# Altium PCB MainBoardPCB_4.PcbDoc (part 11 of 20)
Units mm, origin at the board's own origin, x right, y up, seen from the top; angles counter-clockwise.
Board outline 333.63 x 349.38 mm, 16 copper layers (L1, L2 (GND), L3 (Sign), L4 (GND), L5 (Sign), L6 (PWR/GND), L7(PWR/GND), L8 (Plane_GND), L9 (PWR/GND), L10 (PWR/GND), L11 (PWR/GND), L12 (Sign), L13 (GND), L14 (Sign), L15 (GND), L16), stack 2.502 mm thick; 2205 components, 1648 nets, 8314 pads, 3172 vias.
Unrouted connection lines stored in the file: 5141.
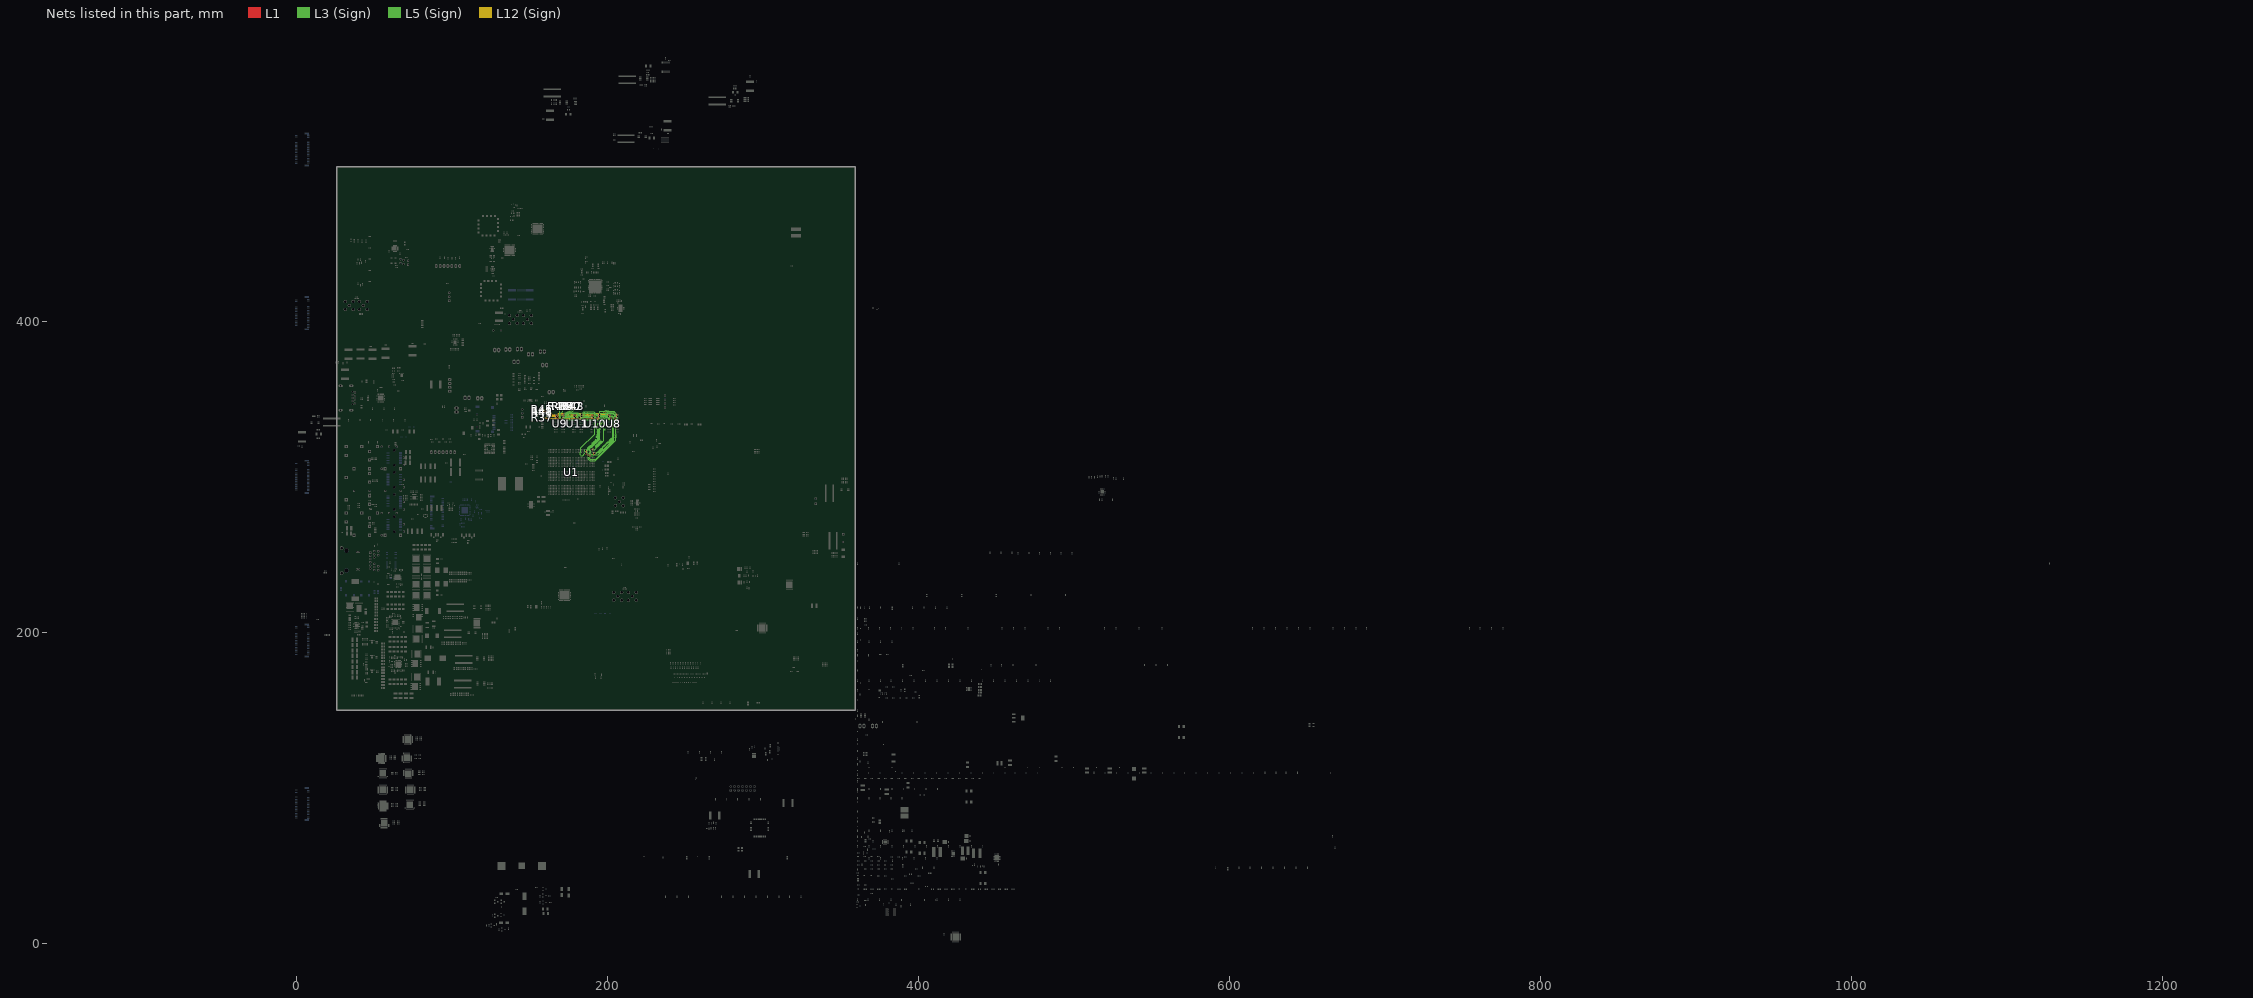
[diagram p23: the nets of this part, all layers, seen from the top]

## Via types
v1: diameter 0.5, hole 0.2, L1 to L16, tented both sides, 1153 vias
v2: diameter 0.5/0.35/0.35/0.35/0.35/0.35/0.35/0.35/0.35/0.35/0.35/0.35/0.35/0.35/0.35/0.5 (per signal layer), hole 0.2, L1 to L16, tented both sides, 548 vias
v3: diameter 0.5, hole 0.2, L1 to L16, 522 vias
v4: diameter 0.5/0.35/0.35/0.35/0.35/0.35/0.35/0.35/0.35/0.35/0.35/0.35/0.35/0.35/0.35/0.5 (per signal layer), hole 0.15, L1 to L16, tented both sides, 266 vias
v5: diameter 0.8, hole 0.4, L1 to L16, tented both sides, 164 vias
v6: diameter 0.35/0/0.35 (per signal layer), hole 0.127, L1 to L3 (Sign), tented both sides, 132 vias
v7: diameter 2.54, hole 1.02, L1 to L16, 125 vias
v8: diameter 1.4, hole 0.5, L1 to L16, tented both sides, 80 vias
v9: diameter 0.35, hole 0.127, L1 to L2 (GND), tented both sides, 36 vias
v10: diameter 0.4, hole 0.2, L1 to L16, 16 vias
v11: diameter 0.25, hole 0.2, L1 to L16, 16 vias
v12: diameter 5, hole 3, L1 to L16, 15 vias
v13: diameter 0.3, hole 0.2, L1 to L16, 15 vias
v14: diameter 0.45, hole 0.15, L1 to L16, 12 vias
v15: diameter 0.5/0.35/0.35/0.35/0.35/0.35/0.35/0.35/0.35/0.35/0.35/0.35/0.35/0.35/0.35/0.45 (per signal layer), hole 0.15, L1 to L16, tented both sides, 10 vias
v16: diameter 0.2/0/0.2 (per signal layer), hole 0.1, L1 to L3 (Sign), tented both sides, 9 vias
v17: diameter 0.4, hole 0.1, L1 to L16, 7 vias
v18: diameter 0.5, hole 0.2, L3 (Sign) to L6 (PWR/GND), tented both sides, 6 vias
v19: diameter 1.65, hole 1.65, L1 to L16, 6 vias
v20: diameter 1.15, hole 1.15, L1 to L16, 6 vias
v21: diameter 0.35/0/0.35 (per signal layer), hole 0.127, L14 (Sign) to L16, tented both sides, 5 vias
v22: diameter 0.2, hole 0.1, L1 to L16, 4 vias
v23: diameter 0.4, hole 0.2, L1 to L16, tented both sides, 2 vias
v24: diameter 0.4, hole 0.15, L1 to L16, 2 vias
v25: diameter 0.508, hole 0.127, L1 to L2 (GND), 2 vias
v26: diameter 0.508, hole 0.127, L2 (GND) to L3 (Sign), 2 vias
v27: diameter 0.5/0.35/0.35/0.35/0.35/0.35/0.35/0.35/0.35/0.35/0.35/0.35/0.35/0.35/0.35/0.5 (per signal layer), hole 0.15, L1 to L16, 2 vias
v28: diameter 0.35, hole 0.127, L3 (Sign) to L6 (PWR/GND), tented both sides, 2 vias
v29: diameter 5.5, hole 3.5, L1 to L16, 1 vias
v30: diameter 0.5/0.35/0.35/0.35/0.35/0.35/0.35/0.35/0.35/0.35/0.35/0.35/0.35/0.35/0.35/0.5 (per signal layer), hole 0.2, L1 to L16, 1 vias
v31: diameter 0.35/0.35/0.35 (per signal layer), hole 0.127, L1 to L3 (Sign), tented both sides, 1 vias
v32: diameter 0.45/0/0.45 (per signal layer), hole 0.15, L1 to L3 (Sign), tented both sides, 1 vias
v33: diameter 0.45/0/0.45 (per signal layer), hole 0.2, L14 (Sign) to L16, tented both sides, 1 vias
v34: diameter 0.35, hole 0.127, L2 (GND) to L3 (Sign), 1 vias
v35: diameter 0.35, hole 0.127, L1 to L2 (GND), 1 vias

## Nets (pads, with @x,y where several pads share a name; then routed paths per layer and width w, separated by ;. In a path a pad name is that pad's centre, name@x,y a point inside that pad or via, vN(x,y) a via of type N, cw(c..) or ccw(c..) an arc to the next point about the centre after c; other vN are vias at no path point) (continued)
DDR4_A3: R37.1 U1.AJ30 U8.N4 U9.N4 U10.N4 U11.N4 | length 99.3
  L1 w0.116: U9.N4@167.676,337.66 168.072,338.057 v4(168.075,338.057) ; U11.N4@179.136,337.66 179.533,338.057 v4(179.535,338.057) ; U1.AJ30@190.397,317.539 v6(190.884,318.027) ; U10.N4@190.597,337.66 190.993,338.057 v4(190.995,338.057) ; U8.N4@202.057,337.66 202.453,338.057 v4(202.456,338.057)
  L1 w0.155: R37.1@158.737,337.967 v1(159.982,337.967)
  L12 (Sign) w0.092: 165.251,337.661 166.76,337.661 167.508,337.661 167.896,338.049 v4(168.075,338.057) ; v4@168.075,338.049 168.821,338.049 169.171,337.698 173.927,337.698 175.389,337.698 cw(c175.389,337.609) 175.479,337.609 175.479,337.545 ccw(c175.568,337.545) 175.568,337.456 175.837,337.456 ccw(c175.837,337.545) 175.927,337.545 175.927,337.698 175.927,337.773 cw(c176.016,337.773) 176.016,337.863 176.285,337.863 cw(c176.285,337.773) 176.374,337.773 176.374,337.698 176.374,337.545 ccw(c176.464,337.545) 176.464,337.456 176.733,337.456 ccw(c176.733,337.545) 176.822,337.545 176.822,337.609 cw(c176.912,337.609) 176.912,337.698 177.046,337.698 177.931,337.698 177.934,337.695 178.053,337.695 178.053,337.698 178.201,337.698 178.201,337.695 178.32,337.695 178.323,337.698 178.831,337.698 179.189,338.057 v4@179.533,338.057 ; v4(179.535,338.057) 180.56,338.057 180.95,337.668 184.651,337.668 185.134,338.15 186.39,338.15 186.616,338.15 cw(c186.616,338.081) 186.685,338.081 186.685,337.958 ccw(c186.754,337.958) 186.754,337.889 186.962,337.889 ccw(c186.962,337.958) 187.031,337.958 187.031,338.15 187.031,338.183 cw(c187.1,338.183) 187.1,338.252 187.308,338.252 cw(c187.308,338.183) 187.377,338.183 187.377,338.15 187.377,337.958 ccw(c187.446,337.958) 187.446,337.889 187.654,337.889 ccw(c187.654,337.958) 187.723,337.958 187.723,338.081 cw(c187.793,338.081) 187.793,338.15 187.897,338.15 189.219,338.15 189.633,337.736 190.504,337.736 190.817,338.049 191.312,338.049 191.662,337.698 193.827,337.698 194.311,337.698 cw(c194.311,337.609) 194.4,337.609 ; 194.4,337.608 ccw(c194.49,337.608) 194.49,337.519 194.759,337.519 ccw(c194.759,337.608) 194.848,337.608 ; 194.848,337.609 cw(c194.938,337.609) 194.938,337.698 195.072,337.698 195.123,337.698 195.458,337.363 196.532,337.363 197.232,337.363 cw(c197.232,337.273) 197.321,337.273 197.321,337.214 ccw(c197.411,337.214) 197.411,337.125 197.68,337.125 ccw(c197.68,337.214) 197.769,337.214 197.769,337.273 cw(c197.859,337.273) 197.859,337.363 197.993,337.363 198.352,337.363 ccw(c198.352,337.452) 198.442,337.452 198.442,337.5 cw(c198.531,337.5) 198.531,337.59 198.8,337.59 cw(c198.8,337.5) 198.89,337.5 198.89,337.363 198.89,337.214 ccw(c198.979,337.214) 198.979,337.125 199.248,337.125 ccw(c199.248,337.214) 199.337,337.214 199.337,337.363 cw(c199.427,337.363) 199.427,337.452 199.696,337.452 cw(c199.696,337.363) 199.785,337.363 199.785,337.214 ccw(c199.875,337.214) 199.875,337.125 200.143,337.125 ccw(c200.143,337.214) 200.233,337.214 200.233,337.273 cw(c200.322,337.273) 200.322,337.363 200.457,337.363 201.112,337.363 201.447,337.698 202.097,337.698 v4(202.456,338.057)
  L12 (Sign) w0.151: v1(159.982,337.967) 160.623,337.967 160.928,337.661 165.251,337.661
  L3 (Sign) w0.092: v6(190.884,318.027) 190.884,317.789 191.329,317.344 191.726,317.344 191.867,317.484 192.147,317.765 192.428,318.046 192.709,318.327 192.919,318.537 ccw(c192.849,318.607) 192.919,318.677 192.123,319.474 cw(c192.193,319.544) 192.123,319.614 192.263,319.755 cw(c192.333,319.684) 192.403,319.755 193.2,318.958 ccw(c193.27,319.028) 193.34,318.958 193.481,319.099 ccw(c193.411,319.169) 193.481,319.239 192.684,320.035 cw(c192.754,320.106) 192.684,320.176 192.825,320.316 cw(c192.895,320.246) 192.965,320.316 193.761,319.52 ccw(c193.832,319.59) 193.902,319.52 194.042,319.66 ccw(c193.972,319.73) 194.042,319.8 193.246,320.597 cw(c193.316,320.667) 193.246,320.737 193.386,320.878 cw(c193.456,320.807) 193.526,320.878 194.323,320.081 ccw(c194.393,320.151) 194.463,320.081 194.604,320.221 ccw(c194.533,320.292) 194.604,320.362 193.807,321.158 cw(c193.877,321.228) 193.807,321.299 193.947,321.439 cw(c194.018,321.369) 194.088,321.439 194.884,320.642 ccw(c194.954,320.713) 195.025,320.642 195.165,320.783 ccw(c195.095,320.853) 195.165,320.923 194.368,321.72 cw(c194.439,321.79) 194.368,321.86 194.509,322 cw(c194.579,321.93) 194.649,322 195.446,321.204 ccw(c195.516,321.274) 195.586,321.204 195.726,321.344 ccw(c195.656,321.414) 195.726,321.485 194.93,322.281 cw(c195,322.351) 194.93,322.422 195.07,322.562 cw(c195.14,322.492) 195.211,322.562 196.007,321.765 ccw(c196.077,321.836) 196.148,321.765 196.288,321.906 ccw(c196.218,321.976) 196.288,322.046 195.491,322.843 cw(c195.562,322.913) 195.491,322.983 195.632,323.123 cw(c195.702,323.053) 195.772,323.123 196.569,322.327 ccw(c196.639,322.397) 196.709,322.327 196.92,322.537 197.2,322.818 197.574,323.192 197.574,329.171 197.574,330.229 cw(c197.673,330.229) 197.673,330.328 198.456,330.328 ccw(c198.456,330.427) 198.555,330.427 198.555,330.626 ccw(c198.456,330.626) 198.456,330.725 197.574,330.725 cw(c197.574,330.824) 197.475,330.824 197.475,331.023 cw(c197.574,331.023) 197.574,331.122 197.75,331.122 ccw(c197.75,331.221) 197.849,331.221 197.849,331.42 ccw(c197.75,331.42) 197.75,331.519 197.574,331.519 cw(c197.574,331.618) 197.475,331.618 197.475,331.817 cw(c197.574,331.817) 197.574,331.916 ccw(c197.574,332.015) 197.673,332.015 197.673,332.214 ccw(c197.574,332.214) 197.574,332.313 197.574,332.511 197.574,334.379 200.822,337.627 202.026,337.627 v4(202.456,338.057)
DDR4_A4: R39.1 U1.AK28 U8.N3 U9.N3 U10.N3 U11.N3 | length 98.4
  L1 w0.116: v4(170.472,338.064) U9.N3@170.876,337.66 ; v30(181.933,338.064) U11.N3@182.336,337.66 ; U1.AK28@191.397,315.539 v6(192.086,315.539) ; v4(193.393,338.064) U10.N3@193.797,337.66 ; v15(204.853,338.064) U8.N3@205.257,337.66
  L1 w0.155: v1(171.229,343.555) R39.1@171.229,344.8
  L5 (Sign) w0.092: 170.437,341.085 169.784,340.433 169.784,338.752 v4(170.472,338.064) 171.003,338.064 171.4,338.46 173.698,338.46 173.832,338.46 ccw(c173.832,338.55) 173.922,338.55 173.922,338.672 cw(c174.011,338.672) 174.011,338.762 174.28,338.762 cw(c174.28,338.672) 174.37,338.672 174.37,338.46 174.37,338.249 ccw(c174.459,338.249) 174.459,338.159 174.728,338.159 ccw(c174.728,338.249) 174.817,338.249 174.817,338.371 cw(c174.907,338.371) 174.907,338.46 175.997,338.46 180.482,338.46 180.878,338.064 v30(181.933,338.064) 182.713,338.064 183.109,338.46 185.801,338.46 185.974,338.46 186.251,338.46 cw(c186.251,338.391) 186.32,338.391 186.32,338.15 ccw(c186.39,338.15) 186.39,338.081 186.597,338.081 ccw(c186.597,338.15) 186.666,338.15 186.666,338.46 186.666,338.77 cw(c186.736,338.77) 186.736,338.84 186.943,338.84 cw(c186.943,338.77) 187.013,338.77 187.013,338.53 ccw(c187.082,338.53) 187.082,338.46 187.82,338.46 191.942,338.46 192.339,338.064 v4(193.393,338.064) 193.924,338.064 194.366,338.506 194.564,338.506 196.327,338.506 cw(c196.327,338.416) 196.417,338.416 196.417,338.348 ccw(c196.506,338.348) 196.506,338.258 196.775,338.258 ccw(c196.775,338.348) 196.864,338.348 196.864,338.506 196.864,338.82 cw(c196.954,338.82) 196.954,338.91 197.223,338.91 cw(c197.223,338.82) 197.312,338.82 197.312,338.595 ccw(c197.402,338.595) 197.402,338.506 197.67,338.506 ccw(c197.67,338.595) 197.76,338.595 197.76,338.82 cw(c197.849,338.82) 197.849,338.91 198.118,338.91 cw(c198.118,338.82) 198.208,338.82 198.208,338.595 ccw(c198.297,338.595) 198.297,338.506 198.566,338.506 ccw(c198.566,338.595) 198.656,338.595 198.656,338.82 cw(c198.745,338.82) 198.745,338.91 199.014,338.91 cw(c199.014,338.82) 199.103,338.82 199.103,338.595 ccw(c199.193,338.595) 199.193,338.506 199.462,338.506 ccw(c199.462,338.595) 199.551,338.595 199.551,338.82 cw(c199.641,338.82) 199.641,338.91 199.909,338.91 cw(c199.909,338.82) 199.999,338.82 199.999,338.595 ccw(c200.088,338.595) 200.088,338.506 200.447,338.506 200.805,338.506 cw(c200.805,338.416) 200.895,338.416 200.895,338.348 ccw(c200.984,338.348) 200.984,338.258 201.253,338.258 ccw(c201.253,338.348) 201.342,338.348 201.342,338.416 cw(c201.432,338.416) 201.432,338.506 201.701,338.506 cw(c201.701,338.416) 201.79,338.416 201.79,338.403 ccw(c201.88,338.403) 201.88,338.314 202.148,338.314 ccw(c202.148,338.403) 202.238,338.403 202.238,338.506 202.238,338.82 cw(c202.327,338.82) 202.327,338.91 202.596,338.91 cw(c202.596,338.82) 202.686,338.82 202.686,338.506 202.686,338.317 ccw(c202.775,338.317) 202.775,338.227 203.044,338.227 ccw(c203.044,338.317) 203.134,338.317 203.134,338.416 cw(c203.223,338.416) 203.223,338.506 203.357,338.506 203.799,338.064 v15(204.853,338.064)
  L5 (Sign) w0.151: 170.437,341.085 171.229,341.878 v1(171.229,343.555)
  L3 (Sign) w0.092: v6(192.086,315.539) 192.317,315.539 192.416,315.539 ccw(c192.416,315.639) 192.515,315.639 192.515,315.688 cw(c192.615,315.688) 192.615,315.787 192.813,315.787 cw(c192.813,315.688) 192.912,315.688 192.912,315.539 192.912,315.189 ccw(c193.012,315.189) 193.012,315.089 193.21,315.089 ccw(c193.21,315.189) 193.309,315.189 193.309,315.44 cw(c193.409,315.44) 193.409,315.539 193.543,315.539 193.684,315.68 ; 193.683,315.68 cw(c193.753,315.75) 193.683,315.821 193.823,315.961 cw(c193.894,315.891) 193.964,315.961 ; 193.964,315.961 194.466,315.459 ccw(c194.536,315.529) 194.606,315.459 194.746,315.6 ccw(c194.676,315.67) 194.746,315.74 194.245,316.241 cw(c194.312,316.309) 194.245,316.376 194.391,316.522 cw(c194.458,316.454) 194.526,316.522 195.027,316.021 ccw(c195.097,316.091) 195.167,316.021 195.308,316.161 ccw(c195.238,316.231) 195.308,316.301 194.806,316.803 cw(c194.874,316.87) 194.806,316.938 194.952,317.083 cw(c195.02,317.016) 195.087,317.083 195.588,316.582 ccw(c195.659,316.652) 195.729,316.582 195.869,316.722 ccw(c195.799,316.793) 195.869,316.863 195.368,317.364 cw(c195.435,317.432) 195.368,317.499 195.514,317.645 cw(c195.581,317.577) 195.649,317.645 196.15,317.144 ccw(c196.22,317.214) 196.29,317.144 196.431,317.284 ccw(c196.36,317.354) 196.431,317.424 195.929,317.926 cw(c195.997,317.993) 195.929,318.06 196.075,318.206 cw(c196.143,318.139) 196.21,318.206 196.711,317.705 ccw(c196.782,317.775) 196.852,317.705 196.992,317.845 ccw(c196.922,317.916) 196.992,317.986 196.491,318.487 cw(c196.558,318.554) 196.491,318.622 196.637,318.768 cw(c196.704,318.7) 196.772,318.768 196.848,318.691 ccw(c196.919,318.761) 196.989,318.691 197.129,318.831 ccw(c197.059,318.901) 197.129,318.971 197.052,319.048 cw(c197.12,319.116) 197.052,319.183 197.198,319.329 cw(c197.265,319.262) 197.333,319.329 197.41,319.252 ccw(c197.48,319.322) 197.55,319.252 197.691,319.393 ccw(c197.62,319.463) 197.691,319.533 197.614,319.61 cw(c197.681,319.677) 197.614,319.745 197.759,319.891 cw(c197.827,319.823) 197.894,319.891 197.971,319.814 ccw(c198.042,319.884) 198.112,319.814 198.252,319.954 ccw(c198.182,320.024) 198.252,320.094 198.175,320.171 cw(c198.243,320.239) 198.175,320.306 198.321,320.452 cw(c198.388,320.385) 198.456,320.452 198.533,320.375 ccw(c198.603,320.445) 198.673,320.375 198.814,320.515 ccw(c198.743,320.586) 198.814,320.656 198.737,320.733 cw(c198.804,320.8) 198.737,320.868 198.882,321.013 cw(c198.95,320.946) 199.017,321.013 199.094,320.937 ccw(c199.164,321.007) 199.235,320.937 199.375,321.077 ccw(c199.305,321.147) 199.375,321.217 199.298,321.294 cw(c199.365,321.362) 199.298,321.429 199.444,321.575 cw(c199.511,321.507) 199.579,321.575 199.656,321.498 ccw(c199.726,321.568) 199.796,321.498 199.936,321.638 ccw(c199.866,321.709) 199.936,321.779 199.859,321.856 cw(c199.927,321.923) 199.859,321.991 200.005,322.136 cw(c200.073,322.069) 200.14,322.136 200.354,321.923 ccw(c200.424,321.993) 200.494,321.923 200.635,322.063 ccw(c200.564,322.133) 200.635,322.203 200.421,322.417 cw(c200.488,322.485) 200.421,322.552 200.567,322.698 cw(c200.634,322.63) 200.702,322.698 200.867,322.532 ccw(c200.938,322.602) 201.008,322.532 201.148,322.672 ccw(c201.078,322.743) 201.148,322.813 200.982,322.979 cw(c201.05,323.046) 200.982,323.113 201.128,323.259 cw(c201.196,323.192) 201.263,323.259 201.429,323.094 ccw(c201.499,323.164) 201.569,323.094 201.71,323.234 ccw(c201.639,323.304) 201.71,323.374 201.544,323.54 cw(c201.611,323.607) 201.544,323.675 201.69,323.821 cw(c201.757,323.753) 201.824,323.821 201.99,323.655 ccw(c202.06,323.725) 202.131,323.655 202.271,323.795 ccw(c202.201,323.865) 202.271,323.936 202.105,324.101 cw(c202.173,324.169) 202.105,324.236 202.251,324.382 cw(c202.318,324.315) 202.386,324.382 202.552,324.216 ccw(c202.622,324.287) 202.692,324.216 202.832,324.357 ccw(c202.762,324.427) 202.832,324.497 202.737,324.593 cw(c202.807,324.663) 202.737,324.733 202.927,324.923 203.434,325.43 203.434,335.975 203.707,336.248 203.707,338.149 203.987,338.43 204.642,338.43 204.853,338.218 v15(204.853,338.064)
DDR4_A5: R41.1 U1.AK27 U8.P5 U9.P5 U10.P5 U11.P5 | length 98
  L1 w0.116: U9.P5@166.876,338.46 167.272,338.857 v4(167.275,338.857) ; U11.P5@178.336,338.46 178.733,338.857 v4(178.735,338.857) ; U10.P5@189.797,338.46 190.193,338.857 v4(190.196,338.857) ; U1.AK27@191.397,314.539 v6(191.884,315.027) ; v4(200.853,338.864) U8.P5@201.257,338.46
  L1 w0.155: R41.1@158.737,341.233 v1(159.982,341.233)
  L12 (Sign) w0.092: 165.251,338.857 166.751,338.857 v4(167.275,338.857) 167.465,339.047 167.688,339.047 167.842,339.201 168.3,339.201 169.159,340.06 173.807,340.06 174.282,339.585 174.472,339.395 cw(c174.409,339.332) 174.472,339.269 174.437,339.233 ccw(c174.5,339.17) 174.437,339.106 174.627,338.916 ccw(c174.69,338.98) 174.753,338.916 174.789,338.952 cw(c174.852,338.889) 174.915,338.952 175.01,338.857 v4(178.735,338.857) 179.053,338.857 179.451,339.255 180.302,339.255 181.127,340.081 184.125,340.081 184.945,339.26 186.576,339.26 187.06,339.26 cw(c187.06,339.191) 187.129,339.191 187.129,339.18 ccw(c187.199,339.18) 187.199,339.111 187.406,339.111 ccw(c187.406,339.18) 187.476,339.18 187.476,339.26 187.476,339.337 cw(c187.545,339.337) 187.545,339.407 187.752,339.407 cw(c187.752,339.337) 187.822,339.337 187.822,339.26 187.822,339.18 ccw(c187.891,339.18) 187.891,339.111 188.099,339.111 ccw(c188.099,339.18) 188.168,339.18 188.168,339.191 cw(c188.237,339.191) 188.237,339.26 188.341,339.26 189.268,339.26 189.672,338.857 v4(190.196,338.857) 190.385,339.047 190.609,339.047 190.763,339.201 191.22,339.201 192.08,340.06 195.846,340.06 196.524,339.382 197.193,339.382 198.16,339.382 cw(c198.16,339.293) 198.25,339.293 198.25,338.968 ccw(c198.339,338.968) 198.339,338.878 198.608,338.878 ccw(c198.608,338.968) 198.697,338.968 198.697,339.382 198.697,339.496 cw(c198.787,339.496) 198.787,339.586 199.056,339.586 cw(c199.056,339.496) 199.145,339.496 199.145,339.382 199.145,338.968 ccw(c199.235,338.968) 199.235,338.878 199.504,338.878 ccw(c199.504,338.968) 199.593,338.968 199.593,339.293 cw(c199.683,339.293) 199.683,339.382 199.817,339.382 200.342,338.857 v4@200.861,338.857
  L12 (Sign) w0.151: v1(159.982,341.233) 160.607,341.233 161.446,340.395 161.491,340.395 163.029,338.857 165.251,338.857
  L3 (Sign) w0.092: 189.328,315.928 189.328,316.31 188.563,317.074 188.563,318.187 188.633,318.257 ccw(c188.563,318.327) 188.633,318.398 188.63,318.401 cw(c188.701,318.471) 188.63,318.541 188.771,318.681 cw(c188.841,318.611) 188.911,318.681 188.984,318.608 189.016,318.576 ccw(c189.087,318.646) 189.157,318.576 189.297,318.717 ccw(c189.227,318.787) 189.297,318.857 189.265,318.889 189.192,318.962 cw(c189.262,319.032) 189.192,319.103 189.332,319.243 cw(c189.402,319.173) 189.473,319.243 189.546,319.17 189.786,318.929 ccw(c189.856,319) 189.926,318.929 190.067,319.07 ccw(c189.997,319.14) 190.067,319.21 189.827,319.45 189.753,319.524 cw(c189.823,319.594) 189.753,319.664 189.894,319.804 cw(c189.964,319.734) 190.034,319.804 190.107,319.731 190.347,319.491 ccw(c190.418,319.561) 190.488,319.491 190.628,319.631 ccw(c190.558,319.701) 190.628,319.772 190.388,320.012 190.315,320.085 cw(c190.385,320.155) 190.315,320.225 190.455,320.366 cw(c190.525,320.296) 190.595,320.366 190.669,320.293 190.909,320.052 ccw(c190.979,320.123) 191.049,320.052 191.19,320.193 ccw(c191.119,320.263) 191.19,320.333 190.949,320.573 190.876,320.647 cw(c190.946,320.717) 190.876,320.787 191.016,320.927 cw(c191.087,320.857) 191.157,320.927 191.23,320.854 191.47,320.614 ccw(c191.54,320.684) 191.611,320.614 191.751,320.754 ccw(c191.681,320.824) 191.751,320.895 191.511,321.135 191.438,321.208 cw(c191.508,321.278) 191.438,321.348 191.578,321.489 cw(c191.648,321.419) 191.718,321.489 191.792,321.415 192.032,321.175 ccw(c192.102,321.245) 192.172,321.175 192.312,321.316 ccw(c192.242,321.386) 192.312,321.456 192.072,321.696 191.999,321.769 cw(c192.069,321.84) 191.999,321.91 192.139,322.05 cw(c192.21,321.98) 192.28,322.05 192.353,321.977 192.593,321.737 ccw(c192.663,321.807) 192.734,321.737 192.874,321.877 ccw(c192.804,321.947) 192.874,322.017 192.634,322.258 192.56,322.331 cw(c192.631,322.401) 192.56,322.471 192.701,322.612 cw(c192.771,322.541) 192.841,322.612 192.914,322.538 193.155,322.298 ccw(c193.225,322.368) 193.295,322.298 193.435,322.439 ccw(c193.365,322.509) 193.435,322.579 193.195,322.819 193.122,322.892 cw(c193.192,322.962) 193.122,323.033 193.262,323.173 cw(c193.332,323.103) 193.403,323.173 193.476,323.1 193.716,322.86 ccw(c193.786,322.93) 193.856,322.86 193.997,323 ccw(c193.927,323.07) 193.997,323.14 193.757,323.38 193.683,323.454 cw(c193.754,323.524) 193.683,323.594 193.824,323.734 cw(c193.894,323.664) 193.964,323.734 194.037,323.661 194.278,323.421 ccw(c194.348,323.491) 194.418,323.421 194.558,323.561 ccw(c194.488,323.632) 194.558,323.702 194.318,323.942 194.245,324.015 cw(c194.315,324.085) 194.245,324.156 194.385,324.296 cw(c194.455,324.226) 194.526,324.296 194.599,324.223 194.839,323.982 ccw(c194.909,324.053) 194.979,323.982 195.12,324.123 ccw(c195.049,324.193) 195.12,324.263 194.95,324.433 cw(c195.02,324.503) 194.95,324.574 195.212,324.836 195.212,330.648 195.631,331.067 195.631,331.483 196.438,332.29 196.438,334.652 200.643,338.857 200.861,338.857 v4(200.853,338.864) ; 189.332,315.928 189.332,315.746 188.956,315.37 188.907,315.37 188.718,315.182 188.718,314.916 188.907,314.728 189.391,314.728 189.605,314.514 190.167,314.514 190.322,314.668 191.091,314.668 191.271,314.847 191.271,315.413 191.419,315.562 191.671,315.562 191.711,315.522 191.711,315.2 v6(191.884,315.027)
DDR4_A6: R43.1 U1.AF27 U8.P2 U9.P2 U10.P2 U11.P2 | length 102.8
  L1 w0.116: U9.P2@171.676,338.46 v4(172.079,338.864) ; U11.P2@183.136,338.46 v4(183.54,338.864) ; U1.AF27@187.397,314.539 v6(187.884,314.052) ; U10.P2@194.597,338.46 v4(195,338.864) ; U8.P2@206.057,338.46 v4(206.461,338.864)
  L1 w0.155: v6(178.481,343.555) R43.1@178.481,344.799
  L5 (Sign) w0.092: v4(172.079,338.864) 173.515,338.864 173.911,339.26 174.6,339.26 174.734,339.26 ccw(c174.734,339.35) 174.823,339.35 174.823,339.393 cw(c174.913,339.393) 174.913,339.482 175.182,339.482 cw(c175.182,339.393) 175.271,339.393 175.271,339.26 175.271,339.128 ccw(c175.361,339.128) 175.361,339.039 175.63,339.039 ccw(c175.63,339.128) 175.719,339.128 175.719,339.171 cw(c175.809,339.171) 175.809,339.26 176.187,339.26 180.228,339.26 181.008,338.48 182.583,338.48 182.966,338.864 v4(183.54,338.864) 183.839,338.864 184.217,339.242 184.404,339.242 184.577,339.242 184.854,339.242 cw(c184.854,339.173) 184.923,339.173 184.923,339.008 ccw(c184.993,339.008) 184.993,338.939 185.2,338.939 ccw(c185.2,339.008) 185.269,339.008 185.269,339.242 185.269,339.477 cw(c185.339,339.477) 185.339,339.546 185.546,339.546 cw(c185.546,339.477) 185.616,339.477 185.616,339.312 ccw(c185.685,339.312) 185.685,339.242 186.195,339.242 191.707,339.242 192.469,338.48 194.043,338.48 194.427,338.864 v4(195,338.864) 195.227,338.864 195.623,339.26 195.77,339.26 196.189,339.26 cw(c196.189,339.171) 196.279,339.171 196.279,339.017 ccw(c196.369,339.017) 196.369,338.927 196.637,338.927 ccw(c196.637,339.017) 196.727,339.017 196.727,339.26 196.727,339.523 cw(c196.816,339.523) 196.816,339.613 197.085,339.613 cw(c197.085,339.523) 197.175,339.523 197.175,339.26 197.175,339.192 ccw(c197.264,339.192) 197.264,339.103 197.533,339.103 ccw(c197.533,339.192) 197.622,339.192 197.622,339.26 197.622,339.523 cw(c197.712,339.523) 197.712,339.613 197.981,339.613 cw(c197.981,339.523) 198.07,339.523 198.07,339.26 198.07,339.192 ccw(c198.16,339.192) 198.16,339.103 198.428,339.103 ccw(c198.428,339.192) 198.518,339.192 198.518,339.26 198.518,339.523 cw(c198.608,339.523) 198.608,339.613 198.876,339.613 cw(c198.876,339.523) 198.966,339.523 198.966,339.26 198.966,339.192 ccw(c199.055,339.192) 199.055,339.103 199.324,339.103 ccw(c199.324,339.192) 199.414,339.192 199.414,339.26 199.414,339.523 cw(c199.503,339.523) 199.503,339.613 199.772,339.613 cw(c199.772,339.523) 199.861,339.523 199.861,339.26 199.861,339.192 ccw(c199.951,339.192) 199.951,339.103 200.22,339.103 ccw(c200.22,339.192) 200.309,339.192 200.309,339.26 200.309,339.295 cw(c200.399,339.295) 200.399,339.385 200.667,339.385 cw(c200.667,339.295) 200.757,339.295 200.757,339.26 ccw(c200.833,339.26) 200.833,339.185 201.129,339.185 ccw(c201.129,339.26) 201.205,339.26 201.429,339.26 203.149,339.26 203.944,338.465 204.078,338.465 ccw(c204.078,338.555) 204.168,338.555 204.168,338.578 cw(c204.257,338.578) 204.257,338.668 204.526,338.668 cw(c204.526,338.578) 204.616,338.578 204.616,338.555 ccw(c204.705,338.555) 204.705,338.465 204.98,338.465 205.489,338.465 205.887,338.864 v4(206.461,338.864)
  L3 (Sign) w0.092: v4(172.079,338.864) 173.022,339.807 174.25,339.807 174.969,340.525 176.05,340.525 176.611,341.085 ; v6(187.884,314.052) 187.884,314.03 188.511,313.403 188.511,311.882 188.986,311.406 192.691,311.406 197.601,316.317 197.671,316.387 ccw(c197.601,316.457) 197.671,316.527 197.317,316.882 cw(c197.387,316.953) 197.317,317.023 197.457,317.163 cw(c197.527,317.093) 197.597,317.163 197.952,316.808 ccw(c198.022,316.878) 198.093,316.808 198.233,316.949 ccw(c198.163,317.019) 198.233,317.089 197.878,317.444 cw(c197.948,317.514) 197.878,317.584 198.018,317.725 cw(c198.088,317.654) 198.159,317.725 198.514,317.37 ccw(c198.584,317.44) 198.654,317.37 198.794,317.51 ccw(c198.724,317.58) 198.794,317.65 198.439,318.005 cw(c198.51,318.076) 198.439,318.146 198.58,318.286 cw(c198.65,318.216) 198.72,318.286 199.075,317.931 ccw(c199.145,318.001) 199.215,317.931 199.356,318.071 ccw(c199.286,318.142) 199.356,318.212 199.001,318.567 cw(c199.071,318.637) 199.001,318.707 199.141,318.847 cw(c199.211,318.777) 199.282,318.847 199.636,318.493 ccw(c199.707,318.563) 199.777,318.493 199.917,318.633 ccw(c199.847,318.703) 199.917,318.773 199.562,319.129 cw(c199.632,319.199) 199.562,319.269 199.702,319.409 cw(c199.772,319.339) 199.843,319.409 200.198,319.054 ccw(c200.268,319.124) 200.338,319.054 200.549,319.265 202.023,320.738 204.01,322.725 204.01,335.707 204.363,336.06 205.816,336.06 206.088,336.332 206.088,337.358 205.791,337.655 205.791,338.496 206.148,338.853 206.449,338.853 v4(206.461,338.864)
  L3 (Sign) w0.151: 176.611,341.085 178.486,342.961 178.486,343.55 v6(178.481,343.555)
DDR4_A7: R45.1 U1.AE27 U8.R5 U9.R5 U10.R5 U11.R5 | length 100.7
  L1 w0.116: U9.R5@166.876,339.26 v4(167.279,339.664) ; U11.R5@178.336,339.26 178.733,339.657 v4(178.735,339.657) ; U1.AE27@186.397,314.539 v6(186.884,315.027) v6@186.884,315.052 ; U10.R5@189.797,339.26 190.193,339.657 v4(190.195,339.657) ; v4(200.853,339.664) U8.R5@201.257,339.26
  L1 w0.155: R45.1@158.737,343.411 v1(159.982,343.411)
  L12 (Sign) w0.092: 165.251,340.06 166.076,340.06 166.576,339.56 167.178,339.56 168.598,340.981 174.981,340.981 175.248,340.981 cw(c175.248,340.891) 175.338,340.891 ccw(c175.427,340.891) 175.427,340.802 175.696,340.802 ccw(c175.696,340.891) 175.785,340.891 cw(c175.875,340.891) 175.875,340.981 176.009,340.981 176.93,340.06 178.332,340.06 v4(178.735,339.657) 178.926,339.657 179.248,339.979 180.276,339.979 181.331,341.033 183.851,341.033 184.027,340.858 186.118,340.858 186.416,340.858 ccw(c186.416,340.927) 186.485,340.927 186.485,340.965 cw(c186.554,340.965) 186.554,341.034 186.762,341.034 cw(c186.762,340.965) 186.831,340.965 186.831,340.858 186.831,340.751 ccw(c186.9,340.751) 186.9,340.682 187.108,340.682 ccw(c187.108,340.751) 187.177,340.751 187.177,340.789 cw(c187.247,340.789) 187.247,340.858 187.35,340.858 188.995,340.858 v4(190.195,339.657) ; v4@190.098,339.56 v4(190.195,339.657) ; v4@200.853,339.657 200.449,339.657 199.466,340.639 199.314,340.639 198.92,340.639 cw(c198.92,340.729) 198.83,340.729 198.83,340.798 ccw(c198.741,340.798) 198.741,340.887 198.472,340.887 ccw(c198.472,340.798) 198.382,340.798 198.382,340.639 198.382,340.481 cw(c198.293,340.481) 198.293,340.392 198.024,340.392 cw(c198.024,340.481) 197.935,340.481 197.935,340.639 197.935,340.798 ccw(c197.845,340.798) 197.845,340.887 197.576,340.887 ccw(c197.576,340.798) 197.487,340.798 197.487,340.639 197.487,340.481 cw(c197.397,340.481) 197.397,340.392 197.129,340.392 cw(c197.129,340.481) 197.039,340.481 197.039,340.639 197.039,340.798 ccw(c196.95,340.798) 196.95,340.887 196.681,340.887 ccw(c196.681,340.798) 196.591,340.798 196.591,340.729 cw(c196.502,340.729) 196.502,340.639 196.367,340.639 196.026,340.981 191.519,340.981 v4(190.195,339.657)
  L12 (Sign) w0.151: v1(159.982,343.411) 161.325,343.411 164.676,340.06 165.251,340.06
  L3 (Sign) w0.092: v6(186.884,315.027) 186.884,315.074 186.615,315.344 185.419,316.539 185.419,317.004 185.788,317.373 186.627,317.373 187.413,318.148 187.554,318.287 187.598,318.331 187.669,318.4 ccw(c187.599,318.471) 187.67,318.541 187.526,318.687 cw(c187.596,318.757) 187.527,318.828 187.668,318.967 cw(c187.738,318.896) 187.808,318.966 188.023,318.749 188.068,318.703 ccw(c188.139,318.772) 188.208,318.702 188.35,318.841 ccw(c188.28,318.912) 188.351,318.981 188.305,319.028 188.083,319.253 cw(c188.154,319.323) 188.084,319.394 188.225,319.533 cw(c188.295,319.462) 188.366,319.532 188.588,319.306 188.629,319.264 ccw(c188.7,319.334) 188.77,319.263 188.911,319.403 ccw(c188.841,319.473) 188.912,319.543 188.871,319.585 188.676,319.782 cw(c188.747,319.852) 188.677,319.922 188.819,320.062 cw(c188.888,319.991) 188.959,320.061 189.153,319.864 189.191,319.826 ccw(c189.262,319.895) 189.331,319.825 189.473,319.964 ccw(c189.403,320.035) 189.474,320.104 189.436,320.142 189.428,320.15 cw(c189.499,320.22) 189.429,320.291 189.571,320.43 cw(c189.64,320.359) 189.711,320.429 ; 189.711,320.429 189.695,320.445 ccw(c189.719,320.469) 189.743,320.445 190.002,320.7 190.066,320.764 190.137,320.834 ccw(c190.067,320.904) 190.138,320.974 189.949,321.166 cw(c190.02,321.235) 189.95,321.306 190.092,321.445 cw(c190.161,321.375) 190.232,321.444 190.491,321.182 190.519,321.153 ccw(c190.589,321.223) 190.659,321.152 190.8,321.292 ccw(c190.731,321.362) 190.801,321.432 190.773,321.461 190.506,321.731 cw(c190.577,321.801) 190.507,321.872 190.649,322.011 cw(c190.718,321.94) 190.789,322.01 191.056,321.739 191.08,321.715 ccw(c191.151,321.785) 191.22,321.714 191.362,321.853 ccw(c191.292,321.924) 191.363,321.994 191.339,322.018 191.072,322.289 cw(c191.142,322.359) 191.073,322.429 191.214,322.569 cw(c191.284,322.498) 191.354,322.568 191.621,322.297 191.642,322.276 ccw(c191.712,322.346) 191.782,322.275 191.923,322.415 ccw(c191.854,322.485) 191.924,322.555 191.904,322.575 191.633,322.85 cw(c191.704,322.92) 191.634,322.991 191.775,323.13 cw(c191.845,323.059) 191.916,323.129 192.187,322.854 192.203,322.838 ccw(c192.274,322.907) 192.343,322.837 192.485,322.976 ccw(c192.415,323.047) 192.486,323.117 192.47,323.133 192.195,323.412 cw(c192.265,323.481) 192.196,323.552 192.337,323.692 cw(c192.407,323.621) 192.477,323.691 192.752,323.412 192.764,323.399 ccw(c192.835,323.469) 192.905,323.398 193.046,323.538 ccw(c192.976,323.608) 193.047,323.678 ; 193.047,323.678 193.063,323.662 cw(c193.092,323.69) 193.064,323.718 193.661,324.307 193.764,324.409 ; 193.764,324.508 193.764,324.409 ; v4(200.853,339.664) 200.804,339.615 200.541,339.615 195.387,334.46 194.068,334.46 193.764,334.156 193.764,333.439 192.865,332.54 192.865,331.238 193.764,330.34 193.764,330.141 cw(c193.764,330.083) 193.822,330.083 193.822,329.802 cw(c193.764,329.802) 193.764,329.744 193.764,329.347 cw(c193.764,329.291) 193.82,329.291 193.82,329.006 cw(c193.764,329.006) 193.764,328.95 193.63,328.95 ccw(c193.63,328.851) 193.531,328.851 193.531,328.652 ccw(c193.63,328.652) 193.63,328.553 193.764,328.553 cw(c193.764,328.497) 193.82,328.497 193.82,328.212 cw(c193.764,328.212) 193.764,328.156 193.764,327.759 cw(c193.764,327.703) 193.82,327.703 193.82,327.418 cw(c193.764,327.418) 193.764,327.362 193.65,327.362 ccw(c193.65,327.263) 193.55,327.263 193.55,327.064 ccw(c193.65,327.064) 193.65,326.965 193.764,326.965 cw(c193.764,326.909) 193.82,326.909 193.82,326.624 cw(c193.764,326.624) 193.764,326.568 192.965,326.568 ccw(c192.965,326.469) 192.865,326.469 192.865,326.27 ccw(c192.965,326.27) 192.965,326.171 193.764,326.171 cw(c193.764,326.115) 193.82,326.115 193.82,325.83 cw(c193.764,325.83) 193.764,325.774 192.965,325.774 ccw(c192.965,325.675) 192.865,325.675 192.865,325.476 ccw(c192.965,325.476) 192.965,325.377 193.764,325.377 194.28,325.377 cw(c194.28,325.278) 194.379,325.278 194.379,325.079 cw(c194.28,325.079) 194.28,324.98 193.863,324.98 ccw(c193.863,324.881) 193.764,324.881 193.764,324.583 193.764,324.409
DDR4_A8: R47.1 U1.AF26 U8.R2 U9.R2 U10.R2 U11.R2 | length 102.5
  L1 w0.116: U9.R2@171.676,339.26 v4(172.079,339.664) ; U11.R2@183.136,339.26 v4(183.54,339.664) ; U1.AF26@187.397,313.539 v6(187.884,313.052) ; U10.R2@194.597,339.26 v4(195,339.664) ; U8.R2@206.057,339.26 v4(206.461,339.664)
  L1 w0.155: v6(177.272,343.555) R47.1@177.272,344.8
  L5 (Sign) w0.092: 170.852,339.343 171.173,339.664 v4(172.079,339.664) 173.045,339.664 174.17,340.789 179.911,340.789 180.239,340.462 181.44,339.26 182.336,339.26 182.74,339.664 v4(183.54,339.664) 184.803,340.927 184.976,340.927 185.253,340.927 cw(c185.253,340.858) 185.322,340.858 185.322,340.794 ccw(c185.391,340.794) 185.391,340.725 185.599,340.725 ccw(c185.599,340.794) 185.668,340.794 185.668,340.858 cw(c185.737,340.858) 185.737,340.927 186.118,340.927 191.377,340.927 193.044,339.26 193.797,339.26 194.2,339.664 v4(195,339.664) 195.408,339.664 195.846,340.102 195.846,340.481 196.292,340.927 200.774,340.927 200.965,340.927 201.355,340.927 cw(c201.355,340.867) 201.415,340.867 201.415,340.875 ; 201.415,340.875 ccw(c201.504,340.875) 201.504,340.786 201.773,340.786 ccw(c201.773,340.875) 201.862,340.875 201.862,340.927 201.862,341.236 cw(c201.952,341.236) 201.952,341.326 202.221,341.326 cw(c202.221,341.236) 202.31,341.236 202.31,340.927 202.31,340.618 ccw(c202.4,340.618) 202.4,340.528 202.669,340.528 ccw(c202.669,340.618) 202.758,340.618 202.758,340.927 202.758,341.236 cw(c202.848,341.236) 202.848,341.326 203.116,341.326 cw(c203.116,341.236) 203.206,341.236 203.206,340.927 203.206,340.618 ccw(c203.295,340.618) 203.295,340.528 203.564,340.528 ccw(c203.564,340.618) 203.654,340.618 203.654,340.837 cw(c203.743,340.837) 203.743,340.927 203.878,340.927 204.038,340.766 204.038,339.801 204.579,339.26 205.257,339.26 205.661,339.664 v4(206.461,339.664)
  L3 (Sign) w0.092: v4(172.079,339.664) 172.613,340.198 173.831,340.198 174.719,341.085 ; v6(187.884,313.052) 187.884,311.416 188.879,310.422 192.299,310.422 205.282,323.405 205.282,324.904 205.282,325.003 ccw(c205.183,325.003) 205.183,325.103 205.032,325.103 cw(c205.032,325.202) 204.932,325.202 204.932,325.4 cw(c205.032,325.4) 205.032,325.5 205.282,325.5 205.732,325.5 ccw(c205.732,325.599) 205.832,325.599 205.832,325.797 ccw(c205.732,325.797) 205.732,325.897 205.282,325.897 205.032,325.897 cw(c205.032,325.996) 204.932,325.996 204.932,326.194 cw(c205.032,326.194) 205.032,326.294 205.282,326.294 205.732,326.294 ccw(c205.732,326.393) 205.832,326.393 205.832,326.591 ccw(c205.732,326.591) 205.732,326.691 205.282,326.691 205.106,326.691 cw(c205.106,326.79) 205.007,326.79 205.007,326.988 cw(c205.106,326.988) 205.106,327.088 205.282,327.088 205.732,327.088 ccw(c205.732,327.187) 205.832,327.187 205.832,327.385 ccw(c205.732,327.385) 205.732,327.485 205.382,327.485 cw(c205.382,327.584) 205.282,327.584 205.282,328.324 205.282,334.975 205.524,335.216 206.013,335.216 206.628,335.831 206.628,337.288 206.042,337.873 206.042,338.3 206.286,338.544 206.327,338.544 206.328,338.543 206.593,338.543 206.594,338.544 206.604,338.544 206.781,338.722 206.781,338.731 206.782,338.997 206.781,339.343 v4(206.461,339.664)
  L3 (Sign) w0.151: 174.719,341.085 175.049,341.085 177.272,343.308 v6(177.272,343.555)
DDR4_A9: R48.1 U1.AG26 U8.R4 U9.R4 U10.R4 U11.R4 | length 100.8
  L1 w0.116: U9.R4@167.676,339.26 v4(168.079,339.664) ; U11.R4@179.136,339.26 179.533,339.657 v4(179.535,339.657) ; U1.AG26@188.397,313.539 v6(188.884,314.027) ; U10.R4@190.597,339.26 190.993,339.657 v3(190.995,339.657) ; v3(201.653,339.664) U8.R4@202.057,339.26
  L1 w0.155: R48.1@158.737,342.322 v1(159.982,342.322)
  L12 (Sign) w0.092: 165.251,339.26 167.443,339.26 167.847,339.664 v4(168.079,339.664) 169.204,340.789 174.119,340.789 175.648,339.26 179.139,339.26 v4(179.535,339.657) 180.231,339.657 181.416,340.841 183.771,340.841 184.551,340.06 186.099,340.06 187.511,340.06 cw(c187.511,339.991) 187.58,339.991 187.58,339.901 ccw(c187.65,339.901) 187.65,339.831 187.857,339.831 ccw(c187.857,339.901) 187.927,339.901 187.927,339.991 cw(c187.996,339.991) 187.996,340.06 188.1,340.06 188.981,340.06 189.802,339.239 190.306,339.239 190.724,339.657 v3(190.995,339.657) 192.127,340.789 195.824,340.789 196.685,339.928 196.736,339.928 197.089,339.928 ccw(c197.089,340.018) 197.178,340.018 197.178,340.099 cw(c197.268,340.099) 197.268,340.189 197.537,340.189 cw(c197.537,340.099) 197.626,340.099 197.626,339.928 197.626,339.674 ccw(c197.716,339.674) 197.716,339.585 197.984,339.585 ccw(c197.984,339.674) 198.074,339.674 198.074,339.839 cw(c198.163,339.839) 198.163,339.928 198.298,339.928 198.611,339.928 ccw(c198.611,340.018) 198.7,340.018 198.7,340.234 cw(c198.79,340.234) 198.79,340.324 199.059,340.324 cw(c199.059,340.234) 199.148,340.234 199.148,339.928 199.148,339.83 ccw(c199.238,339.83) 199.238,339.741 199.506,339.741 ccw(c199.506,339.83) 199.596,339.83 199.596,339.839 cw(c199.686,339.839) 199.686,339.928 199.82,339.928 200.412,339.336 201.325,339.336 v3(201.653,339.664)
  L12 (Sign) w0.151: v1(159.982,342.322) 160.864,342.322 163.926,339.26 165.251,339.26
  L3 (Sign) w0.092: v6(188.884,314.027) 188.884,314.479 188.527,314.836 188.527,315.261 188.827,315.562 188.876,315.562 189.128,315.814 189.128,315.952 189.132,315.955 189.132,316.221 188.944,316.409 188.939,316.409 188.266,317.082 188.266,317.118 188.034,317.35 187.998,317.35 187.973,317.375 187.657,317.375 187.413,317.13 187.413,316.905 187.22,316.713 186.991,316.713 186.76,316.944 186.76,317.167 187.715,318.122 187.935,318.122 194.571,324.759 194.571,325.552 ccw(c194.498,325.552) 194.498,325.625 194.15,325.625 cw(c194.15,325.724) 194.051,325.724 194.051,325.923 cw(c194.15,325.923) 194.15,326.022 194.571,326.022 194.882,326.022 ccw(c194.882,326.121) 194.981,326.121 194.981,326.32 ccw(c194.882,326.32) 194.882,326.419 194.571,326.419 194.15,326.419 cw(c194.15,326.518) 194.051,326.518 194.051,326.717 cw(c194.15,326.717) 194.15,326.816 194.571,326.816 194.882,326.816 ccw(c194.882,326.915) 194.981,326.915 194.981,327.114 ccw(c194.882,327.114) 194.882,327.213 194.571,327.213 194.15,327.213 cw(c194.15,327.312) 194.051,327.312 194.051,327.511 cw(c194.15,327.511) 194.15,327.61 194.571,327.61 194.882,327.61 ccw(c194.882,327.709) 194.981,327.709 194.981,327.908 ccw(c194.882,327.908) 194.882,328.007 194.571,328.007 194.15,328.007 cw(c194.15,328.106) 194.051,328.106 194.051,328.305 cw(c194.15,328.305) 194.15,328.404 194.571,328.404 194.882,328.404 ccw(c194.882,328.503) 194.981,328.503 194.981,328.702 ccw(c194.882,328.702) 194.882,328.801 194.571,328.801 194.15,328.801 cw(c194.15,328.9) 194.051,328.9 194.051,329.099 cw(c194.15,329.099) 194.15,329.198 194.571,329.198 194.882,329.198 ccw(c194.882,329.297) 194.981,329.297 194.981,329.496 ccw(c194.882,329.496) 194.882,329.595 194.67,329.595 cw(c194.67,329.694) 194.571,329.694 194.571,329.794 194.571,330.695 196.222,332.346 196.222,332.376 196.222,332.475 ccw(c196.122,332.475) 196.122,332.574 195.26,332.574 cw(c195.26,332.674) 195.161,332.674 195.161,332.872 cw(c195.26,332.872) 195.26,332.971 196.122,332.971 ccw(c196.122,333.071) 196.222,333.071 196.222,333.269 ccw(c196.122,333.269) 196.122,333.368 195.424,333.368 cw(c195.424,333.468) 195.325,333.468 195.325,333.666 cw(c195.424,333.666) 195.424,333.765 196.122,333.765 ccw(c196.122,333.865) 196.222,333.865 196.222,334.162 196.222,334.796 200.681,339.255 201.536,339.255 201.653,339.372 v3(201.653,339.664)
DDR4_A10: R49.1 U1.AE29 U8.M3 U9.M3 U10.M3 U11.M3 | length 101.4
  L1 w0.116: v4(170.472,337.264) U9.M3@170.876,336.86 ; v4(181.933,337.264) U11.M3@182.336,336.86 ; v6(185.91,317.027) U1.AE29@186.397,316.539 ; v4(193.393,337.264) U10.M3@193.797,336.86 ; v15(204.853,337.264) U8.M3@205.257,336.86
  L1 w0.155: v1(168.812,343.555) R49.1@168.812,344.799
  L5 (Sign) w0.092: 169.377,341.085 169.377,337.887 170.001,337.264 v4(170.472,337.264) 170.709,337.501 171.075,337.501 171.242,337.668 172.6,337.668 173.4,336.868 175.006,336.868 175.145,336.868 cw(c175.145,336.808) 175.204,336.808 ccw(c175.264,336.808) 175.264,336.748 175.542,336.748 ccw(c175.542,336.808) 175.601,336.808 175.601,336.868 175.601,337.113 cw(c175.661,337.113) 175.661,337.173 175.939,337.173 cw(c175.939,337.113) 175.998,337.113 175.998,336.927 ccw(c176.058,336.927) 176.058,336.868 176.479,336.868 179.929,336.868 180.325,337.264 v4(181.933,337.264) 182.776,337.264 183.18,337.668 183.711,337.668 183.937,337.442 183.937,337.051 184.121,336.868 185.89,336.868 186.606,336.868 ccw(c186.606,336.937) 186.675,336.937 186.675,337.037 cw(c186.745,337.037) 186.745,337.106 186.952,337.106 cw(c186.952,337.037) 187.022,337.037 187.022,336.868 187.022,336.698 ccw(c187.091,336.698) 187.091,336.629 187.299,336.629 ccw(c187.299,336.698) 187.368,336.698 187.368,336.798 cw(c187.437,336.798) 187.437,336.868 187.541,336.868 191.389,336.868 191.785,337.264 v4(193.393,337.264) 193.4,337.257 194.34,337.257 194.773,337.689 195.368,337.689 195.512,337.545 196.088,337.545 196.477,337.545 cw(c196.477,337.456) 196.566,337.456 196.566,337.105 ccw(c196.656,337.105) 196.656,337.016 196.925,337.016 ccw(c196.925,337.105) 197.014,337.105 197.014,337.456 cw(c197.104,337.456) 197.104,337.545 197.372,337.545 cw(c197.372,337.456) 197.462,337.456 197.462,337.105 ccw(c197.551,337.105) 197.551,337.016 197.82,337.016 ccw(c197.82,337.105) 197.91,337.105 197.91,337.456 cw(c197.999,337.456) 197.999,337.545 198.268,337.545 cw(c198.268,337.456) 198.357,337.456 198.357,337.105 ccw(c198.447,337.105) 198.447,337.016 198.716,337.016 ccw(c198.716,337.105) 198.805,337.105 198.805,337.456 cw(c198.895,337.456) 198.895,337.545 199.164,337.545 cw(c199.164,337.456) 199.253,337.456 199.253,337.119 ccw(c199.343,337.119) 199.343,337.03 199.611,337.03 ccw(c199.611,337.119) 199.701,337.119 199.701,337.456 cw(c199.79,337.456) 199.79,337.545 200.059,337.545 cw(c200.059,337.456) 200.149,337.456 200.149,337.105 ccw(c200.238,337.105) 200.238,337.016 200.507,337.016 ccw(c200.507,337.105) 200.596,337.105 200.596,337.456 cw(c200.686,337.456) 200.686,337.545 200.82,337.545 201.498,336.868 202.54,336.868 202.936,337.264 v15(204.853,337.264)
  L5 (Sign) w0.151: v1(168.812,343.555) 169.377,342.989 169.377,341.085
  L3 (Sign) w0.092: v6(185.91,317.027) 185.995,316.941 185.995,316.395 188.205,314.185 188.205,313.98 188.747,313.439 190.312,313.439 190.454,313.581 191.069,313.581 191.513,314.025 191.513,314.18 191.731,314.398 192.038,314.398 192.187,314.249 194.226,314.249 199.39,319.413 199.39,319.418 200.219,320.247 200.36,320.387 200.57,320.598 cw(c200.64,320.528) 200.711,320.598 200.966,320.342 ccw(c201.036,320.413) 201.106,320.342 201.247,320.483 ccw(c201.176,320.553) 201.247,320.623 200.991,320.879 cw(c201.061,320.949) 200.991,321.019 201.132,321.159 cw(c201.202,321.089) 201.272,321.159 201.527,320.904 ccw(c201.598,320.974) 201.668,320.904 201.808,321.044 ccw(c201.738,321.114) 201.808,321.185 201.482,321.51 201.157,321.836 cw(c201.227,321.906) 201.157,321.976 201.297,322.117 cw(c201.367,322.046) 201.438,322.117 201.763,321.791 202.089,321.465 ccw(c202.159,321.535) 202.229,321.465 202.37,321.606 ccw(c202.299,321.676) 202.37,321.746 202.044,322.072 201.718,322.397 cw(c201.789,322.467) 201.718,322.538 201.859,322.678 cw(c201.929,322.608) 201.999,322.678 202.325,322.352 202.65,322.027 ccw(c202.72,322.097) 202.791,322.027 202.931,322.167 ccw(c202.861,322.237) 202.931,322.307 202.605,322.633 202.28,322.959 cw(c202.35,323.029) 202.28,323.099 202.42,323.239 cw(c202.49,323.169) 202.56,323.239 202.886,322.914 203.212,322.588 ccw(c203.282,322.658) 203.352,322.588 203.492,322.729 ccw(c203.422,322.799) 203.492,322.869 203.167,323.195 202.841,323.52 cw(c202.911,323.59) 202.841,323.66 202.982,323.801 cw(c203.052,323.731) 203.122,323.801 203.377,323.545 ccw(c203.448,323.616) 203.518,323.545 203.818,323.846 203.818,335.786 204.853,336.822 v15(204.853,337.264)
DDR4_A11: R50.1 U1.AE28 U8.T2 U9.T2 U10.T2 U11.T2 | length 99.6
  L1 w0.116: U9.T2@171.676,340.06 v4(172.079,340.464) ; U11.T2@183.136,340.06 v4(183.54,340.464) ; v6(185.91,315.052) U1.AE28@186.397,315.539 ; U10.T2@194.597,340.06 v4(195,340.464) ; v4(205.653,340.464) U8.T2@206.057,340.06
  L1 w0.155: v6(176.063,343.555) R50.1@176.063,344.8
  L5 (Sign) w0.092: v4(172.079,340.464) 172.3,340.464 173.009,341.173 180.538,341.173 180.633,341.078 ccw(c180.696,341.141) 180.76,341.078 180.824,341.142 cw(c180.888,341.079) 180.951,341.142 181.141,340.952 cw(c181.078,340.889) 181.141,340.826 181.076,340.761 ccw(c181.14,340.698) 181.076,340.635 181.29,340.421 181.643,340.068 182.344,340.068 182.74,340.464 v4(183.54,340.464) 183.774,340.698 184.845,341.77 188.773,341.77 188.862,341.77 ccw(c188.862,341.859) 188.952,341.859 188.952,341.885 cw(c189.042,341.885) 189.042,341.975 189.31,341.975 cw(c189.31,341.885) 189.4,341.885 189.4,341.859 ccw(c189.489,341.859) 189.489,341.77 189.624,341.77 191.402,341.77 193.103,340.068 193.804,340.068 194.2,340.464 v4(195,340.464) 195,342.104 195.123,342.227 198.501,342.227 198.635,342.227 ccw(c198.635,342.316) 198.725,342.316 198.725,342.417 cw(c198.814,342.417) 198.814,342.507 199.083,342.507 cw(c199.083,342.417) 199.173,342.417 199.173,342.227 199.173,342.054 ccw(c199.262,342.054) 199.262,341.964 199.531,341.964 ccw(c199.531,342.054) 199.62,342.054 199.62,342.227 199.62,342.417 cw(c199.71,342.417) 199.71,342.507 199.979,342.507 cw(c199.979,342.417) 200.068,342.417 200.068,342.227 200.068,342.037 ccw(c200.158,342.037) 200.158,341.947 200.427,341.947 ccw(c200.427,342.037) 200.516,342.037 200.516,342.227 200.516,342.417 cw(c200.606,342.417) 200.606,342.507 200.874,342.507 cw(c200.874,342.417) 200.964,342.417 200.964,342.316 ccw(c201.053,342.316) 201.053,342.227 201.231,342.227 204.239,342.227 204.532,341.933 204.532,340.331 204.796,340.068 205.265,340.068 v4(205.653,340.464)
  L3 (Sign) w0.092: v4@172.162,340.547 v4(172.079,340.464) 173.284,340.464 173.905,341.085 ; v6@185.847,314.99 v6(185.91,315.052) 185.561,315.052 184.049,313.539 182.943,313.539 182.423,314.06 182.423,315.761 182.867,316.206 182.867,318.567 191.745,327.444 191.745,334.372 192.317,334.944 192.317,335.956 193.127,336.766 196.05,336.766 200.99,341.706 201.473,341.706 202.307,341.706 ccw(c202.307,341.796) 202.396,341.796 202.396,341.854 cw(c202.486,341.854) 202.486,341.944 202.754,341.944 cw(c202.754,341.854) 202.844,341.854 202.844,341.796 ccw(c202.933,341.796) 202.933,341.706 203.202,341.706 ccw(c203.202,341.796) 203.292,341.796 203.292,341.854 cw(c203.381,341.854) 203.381,341.944 203.65,341.944 cw(c203.65,341.854) 203.739,341.854 203.739,341.796 ccw(c203.829,341.796) 203.829,341.706 204.187,341.706 204.411,341.706 v4(205.653,340.464)
  L3 (Sign) w0.151: 173.905,341.085 176.054,343.234 176.054,343.546 v6(176.063,343.555)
